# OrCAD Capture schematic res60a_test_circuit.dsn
size A; title: RES60A  -  1400-VDC, Precision Resistor Divider; rev: 1.0; note: Datasheet: SLPS764 - AUG 2024 REV DEC 2025
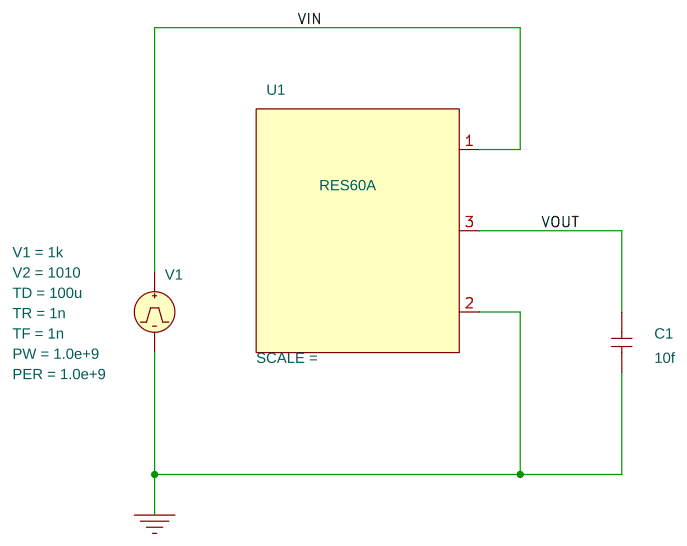
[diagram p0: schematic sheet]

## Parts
C1  10f  [cap196]
U1  RES60A
V1  VPULSE

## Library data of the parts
C1 = C
U1 = RES60A
V1 = VPULSE: AC: 1; AppProp: Pulse$Voltage$0$-1; DC: 1.4k; PER: 1.0e+9; PW: 1.0e+9; TD: 100u; TF: 1n; TR: 1n; V1: 1k; V2: 1010

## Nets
VIN: U1.1(HVIN) V1.1(+)
0: C1.1 U1.2(LVIN) V1.2(-)
VOUT: C1.2 U1.3(MID)
